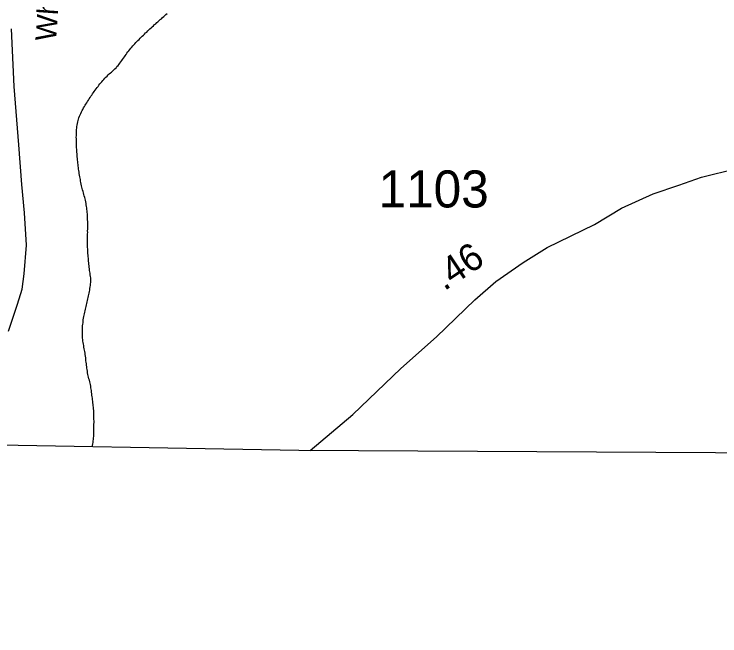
# Model space of a CAD drawing. Extents: x 1950930 to 2061844, y 904556 to 1017002.
# Drawn here: x 1965382 to 1968619, y 906013 to 908865 of the extents above; entities that cross this region are included whole.
import ezdxf

# ---------------------------------------------------------------- set-up
doc = ezdxf.new("R2010")
doc.units = 0
for name, color, linetype in [('Exist Boundary Political CountyLine', 7, 'Continuous'), ('Exist Hydrographic Creek Single Shore', 7, 'Continuous'), ('Exist Road Primary US Structure Standard Bridge CELL', 7, 'Continuous'), ('Exist Road Secondary Type 51 Attributed', 7, 'Continuous'), ('Exist Road Secondary Type 51 Label', 7, 'Continuous'), ('Exist Road Secondary Type 51 Number Label', 7, 'Continuous')]:
    doc.layers.add(name, color=color, linetype=linetype)

msp = doc.modelspace()

# ---------------------------------------------------------------- linework, layer by layer
at = {"layer": 'Exist Boundary Political CountyLine'}
msp.add_lwpolyline([(2014538, 906012.8), (1997082.5, 906396.5), (1993199.8, 906445.3), (1978988.5, 906730.2), (1974332.2, 906819.9), (1966688.7, 906863.1), (1954666.9, 907077.7)], dxfattribs=at)
at = {"layer": 'Exist Hydrographic Creek Single Shore'}
for points in [[(1966026, 908816.8), (1966031.6, 908820.8), (1966036.9, 908825.7), (1966042, 908830.2), (1966047, 908835.1), (1966052.5, 908839.9), (1966057.4, 908844), (1966063, 908848.9), (1966068.5, 908853.8), (1966073.4, 908858.3), (1966078.5, 908863.2), (1966083.9, 908867.2)], [(1965668.4, 908251.4), (1965668.4, 908258.8), (1965667.8, 908265.4), (1965667.8, 908272.7), (1965667.6, 908279.2), (1965667.4, 908286.5), (1965667.4, 908293.5), (1965667.2, 908300.8), (1965667.6, 908307.2), (1965667.4, 908314.5), (1965667.6, 908321), (1965668, 908328.6), (1965668.8, 908335), (1965669.1, 908342.3), (1965669.9, 908349.9), (1965671.1, 908356.2), (1965672.1, 908362.9), (1965673.8, 908370.4), (1965675.4, 908377), (1965677.7, 908383.2), (1965679.5, 908389.8), (1965682.4, 908396.3), (1965685.3, 908402.8), (1965687.9, 908409.2), (1965691.2, 908416), (1965694.5, 908422.5), (1965697.8, 908428), (1965701, 908434.5), (1965704.5, 908440.4), (1965708.2, 908446.8), (1965711.7, 908452.3), (1965715.2, 908458.2), (1965719.3, 908464.5), (1965723.2, 908470.4), (1965726.7, 908476), (1965730.8, 908482.2), (1965734.3, 908487.8), (1965738.6, 908493.6), (1965742, 908499.2), (1965745.9, 908505.1), (1965749.8, 908510.6), (1965754.1, 908516.4), (1965758.5, 908521.8), (1965763, 908527.6), (1965767.3, 908533.1), (1965771.2, 908539), (1965775.5, 908544.5), (1965780.2, 908549.4), (1965784.5, 908554.8), (1965788.8, 908560.7), (1965793.5, 908565.7), (1965798.2, 908571), (1965803.4, 908575.9), (1965808.3, 908580.9), (1965813.4, 908585.8), (1965818.3, 908590.3), (1965823.5, 908595.2), (1965828.8, 908599.2), (1965834.3, 908604), (1965839.4, 908609), (1965844.4, 908613.9), (1965849.5, 908618.4), (1965853.8, 908624.2), (1965858.9, 908629.1), (1965863.2, 908634.6), (1965867.5, 908640.4), (1965871.4, 908645.9), (1965875.7, 908651.7), (1965879.6, 908657.2), (1965883.7, 908663.1), (1965887.6, 908668.6), (1965891.5, 908674.1), (1965895.8, 908679.9), (1965899.7, 908685.4), (1965903.6, 908691.3), (1965907.9, 908696.7), (1965912.2, 908702.6), (1965917.2, 908708.3), (1965921.7, 908712.9), (1965926.6, 908718.7), (1965931.1, 908723.7), (1965936.2, 908728.2), (1965940.5, 908734), (1965945.3, 908739), (1965950.2, 908743.9), (1965955.3, 908748.4), (1965960, 908754.1), (1965964.9, 908758.6), (1965970.1, 908763.6), (1965975.2, 908768.5), (1965979.9, 908773.5), (1965985.2, 908778.3), (1965990.4, 908782.8), (1965994.9, 908787.9), (1966000, 908792.7), (1966005.1, 908797.6), (1966010.7, 908802.5), (1966015.6, 908807), (1966021.1, 908811.9), (1966026, 908816.8)], [(1965722, 907565.2), (1965723.4, 907571.9), (1965724.6, 907579), (1965726.3, 907585.6), (1965727.9, 907593.1), (1965729.3, 907599.4), (1965730, 907606.1), (1965731.2, 907613.3), (1965732.4, 907620.1), (1965733, 907627.3), (1965733.8, 907634), (1965734.3, 907641.3), (1965734.1, 907647.8), (1965733.4, 907655.2), (1965732.8, 907661.7), (1965731.6, 907669.3), (1965731, 907675.9), (1965729.7, 907683.3), (1965728.5, 907689.6), (1965727.3, 907696.3), (1965726.3, 907703.7), (1965725.6, 907710.3), (1965725.2, 907717.7), (1965724.2, 907724.4), (1965723.8, 907731.7), (1965723.2, 907738.3), (1965722.6, 907745.7), (1965722.2, 907752.2), (1965721.1, 907759.7), (1965720.9, 907766.2), (1965720.1, 907773.7), (1965719.9, 907780.2), (1965719.9, 907787.5), (1965719.3, 907794.1), (1965718.9, 907801.9), (1965718.7, 907808.4), (1965718.7, 907815.7), (1965718.5, 907822.3), (1965718.9, 907829.4), (1965718.7, 907836), (1965718.9, 907843.3), (1965718.7, 907849.7), (1965718.9, 907857.4), (1965719.5, 907863.9), (1965719.3, 907871.2), (1965719.7, 907878.9), (1965720.1, 907885.3), (1965719.5, 907892.7), (1965719.7, 907899.2), (1965719.7, 907906.9), (1965719.5, 907913.3), (1965719.1, 907920.7), (1965718.9, 907927.3), (1965718.9, 907934.5), (1965718.3, 907941.2), (1965717.9, 907948.5), (1965717.6, 907955), (1965716.8, 907962.5), (1965716.2, 907969.1), (1965715.2, 907976.5), (1965714.6, 907983.1), (1965713.1, 907989.8), (1965712.3, 907996.9), (1965710.9, 908003.5), (1965709, 908011.1), (1965707.6, 908017.5), (1965705.8, 908024.2), (1965703.9, 908031), (1965702.1, 908037.4), (1965699.8, 908045), (1965698, 908051.4), (1965696.1, 908058.2), (1965694.7, 908064.4), (1965692.8, 908071.2), (1965691.2, 908077.6), (1965689.6, 908085.1), (1965688.1, 908091.8), (1965686.7, 908098.6), (1965685.9, 908106), (1965684.4, 908112.3), (1965683, 908119), (1965681.6, 908126.5), (1965680.9, 908133.1), (1965679.7, 908140.6), (1965678.7, 908146.9), (1965677.7, 908153.5), (1965676.6, 908160.9), (1965676, 908167.5), (1965675.2, 908175), (1965674.2, 908181.6), (1965673.8, 908189), (1965673.2, 908195.6), (1965672.7, 908202.9), (1965671.7, 908209.6), (1965671.1, 908217), (1965670.5, 908223.6), (1965669.7, 908231), (1965669.5, 908237.5), (1965669.1, 908244.9), (1965668.4, 908251.4)], [(1965740.2, 906880.1), (1965741.2, 906886.2), (1965742.5, 906893.7), (1965744.1, 906900.4), (1965744.9, 906907.5), (1965745.5, 906913.9), (1965746.8, 906921.5), (1965747, 906927.9), (1965747.4, 906935.5), (1965748, 906942), (1965748.4, 906949.2), (1965748.2, 906956.1), (1965748.2, 906963.4), (1965748.4, 906969.9), (1965748.4, 906977.3), (1965748.4, 906984.5), (1965748.6, 906991.4), (1965748.6, 906998.7), (1965748.4, 907005.2), (1965748.4, 907012.5), (1965748.2, 907019.1), (1965747.6, 907026.5), (1965747.6, 907032.9), (1965747.6, 907040.6), (1965747, 907047.3), (1965746.4, 907054.7), (1965745.7, 907061.2), (1965744.9, 907068.2), (1965744.3, 907074.9), (1965743.5, 907082.2), (1965742.9, 907088.9), (1965741.8, 907095.5), (1965740.8, 907102.9), (1965739.8, 907109.6), (1965739, 907117), (1965738.4, 907123.7), (1965737.5, 907131), (1965736.5, 907137.7), (1965735.5, 907144.8), (1965734.5, 907151.3), (1965733.4, 907158), (1965732.2, 907165.5), (1965730.8, 907171.8), (1965729.3, 907178.6), (1965727.1, 907185.4), (1965725.2, 907192.6), (1965723.8, 907199.3), (1965722, 907206.1), (1965720.5, 907212.3), (1965719.1, 907219.8), (1965718.1, 907226.5), (1965716.8, 907234), (1965716.2, 907240.2), (1965715.2, 907246.9), (1965714.4, 907254.3), (1965713.8, 907260.8), (1965712.3, 907268.4), (1965711.7, 907275), (1965710.9, 907282.4), (1965710.3, 907289), (1965709.4, 907296.4), (1965708.4, 907303.1), (1965707.4, 907309.3), (1965706.2, 907317.2), (1965704.5, 907323.6), (1965703.5, 907330.1), (1965702.3, 907337.7), (1965701.2, 907344.4), (1965699.8, 907351.5), (1965698.8, 907358.1), (1965697.8, 907364.8), (1965696.9, 907372.2), (1965696.3, 907378.7), (1965695.9, 907386.1), (1965695.7, 907392.7), (1965695.7, 907400), (1965695.5, 907406.5), (1965695.5, 907414.2), (1965695.9, 907421.5), (1965696.1, 907428), (1965696.3, 907435.1), (1965697.1, 907442), (1965698, 907449.2), (1965698.6, 907455.9), (1965699.4, 907463.1), (1965700, 907469.5), (1965701.2, 907477.1), (1965702.9, 907483.7), (1965704.3, 907490), (1965706, 907497.5), (1965707.4, 907504.1), (1965709, 907510.8), (1965711.1, 907517.8), (1965712.5, 907524.4), (1965714.6, 907531), (1965716.2, 907538.1), (1965717.2, 907544.8), (1965719.1, 907551.4), (1965720.7, 907558.5), (1965722, 907565.2)]]:
    msp.add_lwpolyline(points, dxfattribs=at)
at = {"layer": 'Exist Road Secondary Type 51 Attributed'}
for points in [[(1965356.8, 907410.4), (1965397.8, 907535), (1965419.4, 907603.1), (1965428.4, 907674.1), (1965438.8, 907805.8), (1965429.5, 907953.7), (1965417, 908083.7), (1965402.9, 908264.6), (1965382.3, 908532.7), (1965369.9, 908797.6)], [(1966740.7, 906862.8), (1966936.5, 907027.8), (1967156.7, 907238.6), (1967319.5, 907384.7), (1967494.8, 907554.4), (1967592.1, 907637.9), (1967717.3, 907725.6), (1967827.3, 907793.7), (1968044.3, 907899.5), (1968168.8, 907975.4), (1968313.1, 908039.8), (1968431.8, 908081), (1968535.7, 908117.3), (1968695.6, 908156.9), (1968726.5, 908169.7)]]:
    msp.add_lwpolyline(points, dxfattribs=at)

# ---------------------------------------------------------------- texts
at = {"layer": 'Exist Road Primary US Structure Standard Bridge CELL'}
msp.add_text('.46', height=125, rotation=33.636, dxfattribs=at).set_placement((1967354.9, 907593))
at = {"layer": 'Exist Road Secondary Type 51 Label'}
msp.add_text('Wheelers Church Rd.', height=95, rotation=85.9676, dxfattribs=at).set_placement((1965574.1, 908739.2))
at = {"layer": 'Exist Road Secondary Type 51 Number Label'}
msp.add_text('1103', height=170, dxfattribs=at).set_placement((1967053.6, 907977.9))

doc.saveas('drawing.dxf')
